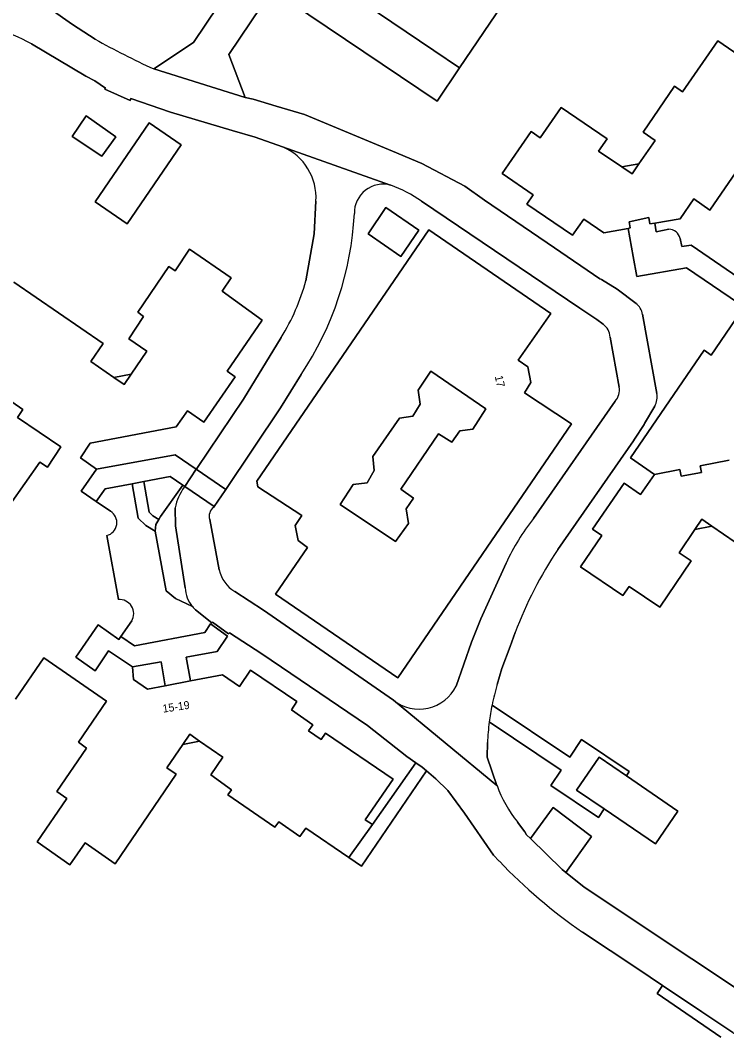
# Model space of a CAD drawing. Extents: x 158132 to 159664, y 385256 to 387218.
# Drawn here: x 159268.1 to 159356.5, y 385997.5 to 386123.9 of the extents above; entities that cross this region are included whole.
import ezdxf

# ---------------------------------------------------------------- set-up
doc = ezdxf.new("R2010")
doc.units = 0
for name, color, linetype in [('IMGEO_Erf', 7, 'Continuous'), ('IMGEO_Groenvoorziening', 7, 'Continuous'), ('IMGEO_Pand', 7, 'Continuous'), ('IMGEO_Pand_nummerreeks', 7, 'Continuous'), ('IMGEO_Pand_overbouw', 7, 'Continuous'), ('IMGEO_Parkeervlak_open', 7, 'Continuous'), ('IMGEO_Rijbaan_lokaal_gesloten', 7, 'Continuous'), ('IMGEO_Rijbaan_lokaal_open', 7, 'Continuous'), ('IMGEO_Voetpad_open', 7, 'Continuous')]:
    doc.layers.add(name, color=color, linetype=linetype)

msp = doc.modelspace()

# ---------------------------------------------------------------- linework, layer by layer
at = {"layer": 'IMGEO_Erf'}
for points in [[(159343.38, 386105.59), (159344.67, 386104.72), (159345.53, 386105.96)], [(159311.64, 386097.21), (159313.88, 386100.48), (159317.99, 386097.66), (159315.76, 386094.39)], [(159304.07, 386058.01), (159302.92, 386058.89), (159302.53, 386060.76), (159303.35, 386062.02), (159297.85, 386065.6), (159297.72, 386066.29), (159319.25, 386097.72), (159334.52, 386087.24), (159330.43, 386081.4), (159331.64, 386080.57), (159332.01, 386078.61), (159331.22, 386077.34), (159337.1, 386073.46), (159315.37, 386041.72), (159300.08, 386052.17)], [(159282.02, 386079.67), (159279.83, 386079.26), (159281.13, 386078.37)], [(159319.51, 386080.03), (159317.92, 386077.68), (159318.15, 386075.9), (159317.24, 386074.44), (159315.56, 386074.17), (159312.23, 386069.39), (159312.42, 386067.65), (159311.55, 386066.1), (159309.77, 386065.9), (159308.16, 386063.39), (159315.06, 386058.75), (159316.71, 386061.02), (159316.42, 386062.85), (159317.32, 386064.16), (159315.75, 386065.3), (159320.46, 386072.2), (159322.13, 386071.19), (159323.13, 386072.6), (159324.73, 386072.79), (159326.38, 386075.35)], [(159288.48, 386065.79), (159286.91, 386066.86), (159283.6, 386066.24), (159284.26, 386062.42), (159284.74, 386061.95), (159285.47, 386061.5), (159285.7, 386061.87)], [(159354.64, 386060.67), (159353.37, 386061.54), (159352.51, 386060.27)], [(159286.27, 386040.73), (159285.77, 386043.7), (159282.16, 386043.08), (159282.32, 386041.52), (159284.07, 386040.32)], [(159288.48, 386033.4), (159290.58, 386033.81), (159289.35, 386034.67)]]:
    msp.add_lwpolyline(points, close=True, dxfattribs=at)
for points in [[(159341.04, 386085.92), (159340.24, 386086.49), (159338.14, 386087.92), (159318.33, 386101.28)], [(159349.25, 386097.78), (159347.68, 386097.45), (159347.5, 386098.55), (159346.9, 386098.45), (159346.76, 386099.24), (159344.29, 386098.71), (159344.42, 386097.94), (159344.16, 386097.89), (159344.79, 386094.36), (159345.24, 386091.86), (159351.47, 386092.96), (159357.99, 386088.53), (159358.22, 386087.41), (159360.15, 386090.24), (159352.04, 386095.79), (159350.88, 386095.61), (159350.69, 386096.64)], [(159343.05, 386078.05), (159341.93, 386084.31)], [(159303.27, 386079.64), (159300.68, 386075.48), (159293.87, 386065.25), (159293.79, 386065.14), (159292.4, 386063.12), (159292.32, 386063.02)], [(159332.33, 386061.62), (159342.55, 386076.3)], [(159289.67, 386050.63), (159287.54, 386051.65), (159286.41, 386052.6), (159285.01, 386060.05), (159283.83, 386060.77), (159282.88, 386061.69), (159282.14, 386065.97), (159278.77, 386065.34), (159277.63, 386063.76), (159279.42, 386062.54)], [(159291.84, 386061.5), (159293.03, 386055.21)], [(159278.96, 386059.5), (159280.41, 386051.49)], [(159322.67, 386040.68), (159324.6, 386046.17), (159325.76, 386049.08), (159327.4, 386052.75), (159328.9, 386056.06)], [(159294.99, 386052.52), (159298.58, 386050.18), (159314.83, 386038.94)], [(159298.36, 386044.7), (159294.33, 386047.36), (159294.19, 386047.22), (159292.17, 386048.69), (159292.11, 386048.58), (159290.06, 386050.21)], [(159282.08, 386048.83), (159280.74, 386046.88), (159282.42, 386045.71), (159291.21, 386047.37), (159291.95, 386048.45), (159294.08, 386046.91), (159292.76, 386044.99), (159288.89, 386044.29), (159289.43, 386041.33), (159293.44, 386042.08), (159295.55, 386040.63), (159296.96, 386042.66), (159302.74, 386038.75), (159302.05, 386037.7), (159304.73, 386035.83), (159304.21, 386035.09), (159305.76, 386034.03), (159306.3, 386034.79), (159314.77, 386029.04), (159311.3, 386023.98), (159312.18, 386023.39), (159317.63, 386031.1), (159316.51, 386031.9), (159311.58, 386035.75), (159298.36, 386044.7)]]:
    msp.add_lwpolyline(points, dxfattribs=at)
for centre, radius, start, end in [((159313.52, 386099.82), 3.59, 74.6472, 181.3944), ((159308.31, 386086.58), 17.8, 55.6991, 69.7327), ((159270.35, 386101.72), 39.63, 326.1427, 357.1243), ((159349.27, 386096.33), 1.44, 12.0964, 91.081), ((159339.73, 386084.14), 2.21, 4.4468, 53.6926), ((159340.96, 386077.7), 2.12, 318.7172, 9.5991), ((159293.12, 386061.93), 1.35, 126.2293, 198.6545), ((159278.55, 386061.12), 1.67, 284.0563, 58.6242), ((159353.6, 386044.66), 27.2, 141.4288, 155.2241), ((159297.1, 386056.12), 4.18, 192.6758, 239.5387), ((159280.56, 386049.73), 1.77, 329.3209, 95.1105), ((159292.73, 386053.09), 3.93, 218.819, 227.2504), ((159318.04, 386042.98), 5.17, 231.5281, 333.5898)]:
    msp.add_arc(centre, radius, start, end, dxfattribs=at)
at = {"layer": 'IMGEO_Groenvoorziening'}
for points in [[(159335.95, 386136.95), (159323.1, 386117.95), (159320.28, 386113.77), (159299.63, 386127.71), (159294.22, 386119.61), (159296.27, 386114.24), (159297.27, 386114.02), (159300.16, 386113.16), (159303.71, 386112.11), (159314.7, 386107.55), (159318.37, 386106), (159323.74, 386103.16), (159326.21, 386101.41), (159334.98, 386095.47), (159340.64, 386091.6), (159340.83, 386091.48), (159342.82, 386090.3), (159345.16, 386088.49)], [(159284.83, 386117.81), (159289.8, 386121.12), (159295.91, 386130.21)], [(159269.49, 386127.04), (159274.68, 386123.36), (159277.5, 386121.54)], [(159300.96, 386108.09), (159297.51, 386109.27), (159294.64, 386110.12), (159286.92, 386112.41), (159281.99, 386114.1), (159281.87, 386113.87), (159278.73, 386115.28), (159278.8, 386115.43), (159277.49, 386116.31), (159276.36, 386116.9), (159269.53, 386120.94)], [(159347.56, 386108.88), (159346.06, 386109.9), (159349.99, 386115.64), (159350.99, 386114.96), (159355.38, 386121.31), (159358.06, 386119.48), (159358.15, 386119.59), (159359.43, 386118.64), (159359.56, 386118.8), (159362.52, 386116.78), (159359.88, 386112.88), (159361, 386112.06), (159359.19, 386109.35), (159360.84, 386108.18), (159358.78, 386105.2), (159358.15, 386105.62), (159354.39, 386100.18), (159352.38, 386101.59), (159350.66, 386099.08), (159347.5, 386098.55), (159347.68, 386097.45), (159349.25, 386097.78)], [(159357.99, 386088.53), (159351.47, 386092.96), (159345.24, 386091.86), (159344.79, 386094.36), (159344.16, 386097.89), (159341.12, 386097.34), (159338.63, 386099.05), (159337.2, 386097.02), (159331.52, 386100.9), (159332.29, 386102.07), (159328.43, 386104.75), (159332.03, 386109.98), (159333.19, 386109.21), (159335.8, 386113.01), (159341.54, 386109.07), (159340.47, 386107.55), (159343.38, 386105.59), (159345.53, 386105.96), (159347.56, 386108.88)], [(159303.85, 386091.34), (159304.92, 386097.21), (159305.13, 386101.28)], [(159350.69, 386096.64), (159350.88, 386095.61), (159352.04, 386095.79), (159360.15, 386090.24)], [(159267.32, 386091.16), (159278.51, 386083.48), (159276.96, 386081.24), (159279.83, 386079.26), (159282.02, 386079.67), (159283.99, 386082.54), (159281.73, 386084.09), (159283.56, 386086.86), (159282.83, 386087.4), (159286.72, 386093.11), (159287.51, 386092.58), (159289.32, 386095.28), (159294.51, 386091.71), (159293.41, 386090.03), (159298.38, 386086.42), (159294.02, 386080.05), (159295.04, 386079.34), (159291.09, 386073.68), (159289.05, 386075.07), (159287.64, 386073.08), (159276.87, 386071.04), (159275.67, 386069.23), (159277.67, 386067.81), (159287.5, 386069.59), (159290.15, 386067.78), (159290.22, 386067.89), (159296.05, 386076.54), (159300.78, 386084.27)], [(159357.54, 386058.69), (159354.64, 386060.67), (159352.51, 386060.27), (159350.55, 386057.34), (159352.05, 386056.33), (159348.13, 386050.57), (159344.31, 386053.12), (159343.5, 386052), (159338.23, 386055.58), (159340.9, 386059.52), (159339.73, 386060.28), (159343.67, 386066.03), (159345.73, 386064.62), (159347.45, 386067.15), (159344.46, 386069.2), (159353.67, 386082.67), (159354.56, 386082.06), (159358.22, 386087.41)], [(159345.97, 386087.15), (159347.76, 386077.26)], [(159266.82, 386063.33), (159270.59, 386068.68), (159271.54, 386068.04), (159273.23, 386070.6), (159267.78, 386074.27), (159268.46, 386075.27), (159262.08, 386079.66)], [(159347.5, 386075.67), (159346.23, 386073.49), (159346.18, 386073.39), (159344.97, 386071.54), (159344.83, 386071.35), (159335.38, 386057.77)], [(159330.04, 386047.37), (159329.4, 386045.64), (159328.38, 386042.89), (159327.79, 386040.9)], [(159328.06, 386018.79), (159327.35, 386019.57), (159323.69, 386024.8), (159321.62, 386027.66), (159320.14, 386029.09), (159318.95, 386030.1), (159310.82, 386018.18), (159309.25, 386019.25), (159303.84, 386022.94), (159303.11, 386021.91), (159300.48, 386023.72), (159299.98, 386023.05), (159294.11, 386027.11), (159294.56, 386027.73), (159291.98, 386029.58), (159293.49, 386031.79), (159290.58, 386033.81), (159288.48, 386033.4), (159286.49, 386030.49), (159287.63, 386029.66), (159280.03, 386018.47), (159276.27, 386021.08), (159274.35, 386018.34), (159270.24, 386021.21), (159273.95, 386026.65), (159272.7, 386027.51), (159276.43, 386032.95), (159275.41, 386033.66), (159278.92, 386038.79), (159271.08, 386044.23), (159267.53, 386039.05)], [(159327.15, 386038.3), (159336.86, 386031.79), (159338.35, 386034.02), (159344.32, 386030.02), (159343.95, 386029.47), (159350.4, 386025.07), (159347.58, 386020.96), (159341.17, 386025.33), (159340.46, 386024.26), (159334.49, 386028.26), (159335.78, 386030.19), (159326.8, 386036.2)], [(159326.57, 386033.62), (159326.52, 386031.8), (159327.77, 386028.26)], [(159330.33, 386023.7), (159331.27, 386022.46), (159331.46, 386022.11), (159331.94, 386021.63), (159334.78, 386025.51), (159339.6, 386021.9), (159336.36, 386017.41), (159338.61, 386015.61), (159349.29, 386008.47), (159354.98, 386004.72), (159362.07, 386000), (159362.67, 385999.6), (159365, 385998.05), (159365.02, 385998.03), (159366.81, 385996.83), (159367.48, 385996.37)], [(159355.76, 385996.83), (159347.79, 386002.25), (159348.48, 386003.28), (159345.38, 386005.36), (159338.45, 386009.93)]]:
    msp.add_lwpolyline(points, dxfattribs=at)
for points in [[(159278.36, 386106.9), (159274.62, 386109.39), (159276.38, 386111.95), (159280.1, 386109.33)], [(159277.51, 386101.19), (159284.25, 386111.07), (159288.26, 386108.34), (159281.52, 386098.46)]]:
    msp.add_lwpolyline(points, close=True, dxfattribs=at)
for centre, radius, start, end in [((159260.07, 386104.26), 19.18, 60.4425, 75.3025), ((159329.26, 386214.28), 106.21, 240.8363, 245.2733), ((159298.22, 386101.73), 6.92, 356.2434, 66.664), ((159349.27, 386096.33), 1.44, 12.0964, 91.081), ((159279.05, 386097.91), 25.66, 327.8886, 345.1676), ((159343.93, 386086.83), 2.06, 8.7647, 53.5626), ((159345.52, 386076.81), 2.28, 330.159, 11.5367), ((159378.27, 386029.15), 51.56, 146.2907, 159.3077), ((159358.35, 386032.1), 31.81, 163.9268, 168.7575), ((159359.21, 386031.92), 32.69, 172.4767, 177.0142), ((159342.69, 386033.65), 15.86, 199.8565, 218.834), ((159378.7, 386067.59), 70.32, 223.9382, 235.0831)]:
    msp.add_arc(centre, radius, start, end, dxfattribs=at)
at = {"layer": 'IMGEO_Pand'}
for points in [[(159358.06, 386119.48), (159355.38, 386121.31), (159350.99, 386114.96), (159349.99, 386115.64), (159346.06, 386109.9), (159347.56, 386108.88), (159345.53, 386105.96), (159344.67, 386104.72), (159343.38, 386105.59), (159340.47, 386107.55), (159341.54, 386109.07), (159335.8, 386113.01), (159333.19, 386109.21), (159332.03, 386109.98), (159328.43, 386104.75), (159332.29, 386102.07), (159331.52, 386100.9), (159337.2, 386097.02), (159338.63, 386099.05), (159341.12, 386097.34), (159344.16, 386097.89), (159344.42, 386097.94), (159344.29, 386098.71), (159346.76, 386099.24), (159346.9, 386098.45), (159347.5, 386098.55), (159350.66, 386099.08), (159352.38, 386101.59), (159354.39, 386100.18), (159358.15, 386105.62)], [(159279.42, 386062.54), (159277.63, 386063.76), (159275.78, 386065.03), (159277.67, 386067.81), (159275.67, 386069.23), (159276.87, 386071.04), (159287.64, 386073.08), (159289.05, 386075.07), (159291.09, 386073.68), (159295.04, 386079.34), (159294.02, 386080.05), (159298.38, 386086.42), (159293.41, 386090.03), (159294.51, 386091.71), (159289.32, 386095.28), (159287.51, 386092.58), (159286.72, 386093.11), (159282.83, 386087.4), (159283.56, 386086.86), (159281.73, 386084.09), (159283.99, 386082.54), (159282.02, 386079.67), (159281.13, 386078.37), (159279.83, 386079.26), (159276.96, 386081.24), (159278.51, 386083.48), (159267.32, 386091.16)], [(159358.22, 386087.41), (159354.56, 386082.06), (159353.67, 386082.67), (159344.46, 386069.2), (159347.45, 386067.15), (159350.65, 386067.76), (159350.82, 386066.93), (159353.33, 386067.39), (159353.17, 386068.21), (159356.81, 386068.93)], [(159262.08, 386079.66), (159268.46, 386075.27), (159267.78, 386074.27), (159273.23, 386070.6), (159271.54, 386068.04), (159270.59, 386068.68), (159266.82, 386063.33)], [(159356.81, 386068.93), (159353.17, 386068.21), (159353.33, 386067.39), (159350.82, 386066.93), (159350.65, 386067.76), (159347.45, 386067.15), (159345.73, 386064.62), (159343.67, 386066.03), (159339.73, 386060.28), (159340.9, 386059.52), (159338.23, 386055.58), (159343.5, 386052), (159344.31, 386053.12), (159348.13, 386050.57), (159352.05, 386056.33), (159350.55, 386057.34), (159352.51, 386060.27), (159353.37, 386061.54), (159354.64, 386060.67), (159357.54, 386058.69)], [(159280.41, 386051.49), (159278.96, 386059.5)], [(159267.53, 386039.05), (159271.08, 386044.23), (159278.92, 386038.79), (159275.41, 386033.66), (159276.43, 386032.95), (159272.7, 386027.51), (159273.95, 386026.65), (159270.24, 386021.21), (159274.35, 386018.34), (159276.27, 386021.08), (159280.03, 386018.47), (159287.63, 386029.66), (159286.49, 386030.49), (159288.48, 386033.4), (159289.35, 386034.67), (159290.58, 386033.81), (159293.49, 386031.79), (159291.98, 386029.58), (159294.56, 386027.73), (159294.11, 386027.11), (159299.98, 386023.05), (159300.48, 386023.72), (159303.11, 386021.91), (159303.84, 386022.94), (159309.25, 386019.25), (159312.18, 386023.39), (159311.3, 386023.98), (159314.77, 386029.04), (159306.3, 386034.79), (159305.76, 386034.03), (159304.21, 386035.09), (159304.73, 386035.83), (159302.05, 386037.7), (159302.74, 386038.75), (159296.96, 386042.66), (159295.55, 386040.63), (159293.44, 386042.08), (159289.43, 386041.33), (159286.27, 386040.73), (159284.07, 386040.32), (159282.32, 386041.52), (159282.16, 386043.08), (159279.19, 386045.1), (159277.51, 386042.61), (159275.11, 386044.3), (159277.89, 386048.33), (159280.47, 386046.49), (159280.74, 386046.88), (159282.08, 386048.83)]]:
    msp.add_lwpolyline(points, dxfattribs=at)
for points in [[(159278.36, 386106.9), (159280.1, 386109.33), (159276.38, 386111.95), (159274.62, 386109.39)], [(159277.51, 386101.19), (159281.52, 386098.46), (159288.26, 386108.34), (159284.25, 386111.07)], [(159315.76, 386094.39), (159317.99, 386097.66), (159313.88, 386100.48), (159311.64, 386097.21)], [(159337.1, 386073.46), (159331.22, 386077.34), (159332.01, 386078.61), (159331.64, 386080.57), (159330.43, 386081.4), (159334.52, 386087.24), (159319.25, 386097.72), (159297.72, 386066.29), (159297.85, 386065.6), (159303.35, 386062.02), (159302.53, 386060.76), (159302.92, 386058.89), (159304.07, 386058.01), (159300.08, 386052.17), (159315.37, 386041.72)], [(159319.51, 386080.03), (159326.38, 386075.35), (159324.73, 386072.79), (159323.13, 386072.6), (159322.13, 386071.19), (159320.46, 386072.2), (159315.75, 386065.3), (159317.32, 386064.16), (159316.42, 386062.85), (159316.71, 386061.02), (159315.06, 386058.75), (159308.16, 386063.39), (159309.77, 386065.9), (159311.55, 386066.1), (159312.42, 386067.65), (159312.23, 386069.39), (159315.56, 386074.17), (159317.24, 386074.44), (159318.15, 386075.9), (159317.92, 386077.68)], [(159343.95, 386029.47), (159340.54, 386031.8), (159337.72, 386027.68), (159341.17, 386025.33), (159347.58, 386020.96), (159350.4, 386025.07)]]:
    msp.add_lwpolyline(points, close=True, dxfattribs=at)
for centre, radius, start, end in [((159278.55, 386061.12), 1.67, 284.0563, 58.6242), ((159280.56, 386049.73), 1.77, 329.3209, 95.1105)]:
    msp.add_arc(centre, radius, start, end, dxfattribs=at)
at = {"layer": 'IMGEO_Pand_overbouw'}
for points in [[(159345.53, 386105.96), (159343.38, 386105.59), (159344.67, 386104.72)], [(159279.83, 386079.26), (159281.13, 386078.37), (159282.02, 386079.67)], [(159352.51, 386060.27), (159354.64, 386060.67), (159353.37, 386061.54)], [(159288.48, 386033.4), (159290.58, 386033.81), (159289.35, 386034.67), (159288.48, 386033.4)]]:
    msp.add_lwpolyline(points, close=True, dxfattribs=at)
for points in [[(159349.25, 386097.78), (159347.68, 386097.45), (159347.5, 386098.55), (159346.9, 386098.45), (159346.76, 386099.24), (159344.29, 386098.71), (159344.42, 386097.94), (159344.16, 386097.89), (159344.79, 386094.36), (159345.24, 386091.86), (159351.47, 386092.96), (159357.99, 386088.53), (159358.22, 386087.41), (159360.15, 386090.24), (159352.04, 386095.79)], [(159352.04, 386095.79), (159350.88, 386095.61), (159350.69, 386096.64)]]:
    msp.add_lwpolyline(points, dxfattribs=at)
msp.add_arc((159349.27, 386096.33), 1.44, 12.0964, 91.081, dxfattribs=at)
at = {"layer": 'IMGEO_Parkeervlak_open'}
for points in [[(159299.63, 386127.71), (159320.28, 386113.77), (159323.1, 386117.95), (159319.88, 386120.12), (159302.45, 386131.89)], [(159331.94, 386021.63), (159335.91, 386017.76), (159336.36, 386017.41), (159339.6, 386021.9), (159334.78, 386025.51)]]:
    msp.add_lwpolyline(points, close=True, dxfattribs=at)
for points in [[(159288.64, 386065.53), (159288.71, 386065.63), (159288.48, 386065.79), (159285.7, 386061.87), (159285.47, 386061.5), (159285.09, 386060.88), (159285.01, 386060.05), (159286.41, 386052.6), (159287.54, 386051.65), (159289.67, 386050.63)], [(159287.56, 386060.73), (159287.53, 386062.97)], [(159288.78, 386052.98), (159287.56, 386060.73)]]:
    msp.add_lwpolyline(points, dxfattribs=at)
for centre, radius, start, end in [((159293.6, 386061.86), 6.17, 143.5055, 169.6334), ((159292.79, 386053.15), 4.02, 182.547, 218.918)]:
    msp.add_arc(centre, radius, start, end, dxfattribs=at)
at = {"layer": 'IMGEO_Rijbaan_lokaal_gesloten'}
for points in [[(159277.5, 386121.54), (159274.68, 386123.36), (159269.49, 386127.04)], [(159269.53, 386120.94), (159276.36, 386116.9), (159277.49, 386116.31), (159278.8, 386115.43), (159278.73, 386115.28), (159281.87, 386113.87), (159281.99, 386114.1), (159286.92, 386112.41), (159294.64, 386110.12), (159297.51, 386109.27), (159300.96, 386108.09), (159314.47, 386103.28)], [(159345.16, 386088.49), (159342.82, 386090.3), (159340.83, 386091.48), (159340.64, 386091.6), (159334.98, 386095.47), (159326.21, 386101.41), (159323.74, 386103.16), (159318.37, 386106), (159314.7, 386107.55), (159303.71, 386112.11), (159300.16, 386113.16), (159297.27, 386114.02), (159296.27, 386114.24), (159284.83, 386117.81)], [(159314.47, 386103.28), (159300.96, 386108.09)], [(159305.13, 386101.28), (159304.92, 386097.21), (159303.85, 386091.34)], [(159318.33, 386101.28), (159338.14, 386087.92), (159340.24, 386086.49), (159341.04, 386085.92)], [(159347.76, 386077.26), (159345.97, 386087.15)], [(159341.93, 386084.31), (159343.05, 386078.05)], [(159300.78, 386084.27), (159296.05, 386076.54), (159290.22, 386067.89), (159290.15, 386067.78), (159293.87, 386065.25), (159300.68, 386075.48), (159303.27, 386079.64)], [(159342.55, 386076.3), (159332.33, 386061.62)], [(159335.38, 386057.77), (159344.83, 386071.35), (159344.97, 386071.54), (159346.18, 386073.39), (159346.23, 386073.49), (159347.5, 386075.67)], [(159292.32, 386063.02), (159292.4, 386063.12), (159288.71, 386065.63), (159288.64, 386065.53)], [(159287.53, 386062.97), (159287.56, 386060.73), (159288.78, 386052.98)], [(159293.03, 386055.21), (159291.84, 386061.5)], [(159328.9, 386056.06), (159327.4, 386052.75), (159325.76, 386049.08), (159324.6, 386046.17), (159322.67, 386040.68)], [(159298.58, 386050.18), (159294.99, 386052.52)], [(159290.06, 386050.21), (159292.11, 386048.58), (159292.17, 386048.69), (159294.19, 386047.22), (159294.33, 386047.36), (159298.36, 386044.7), (159311.58, 386035.75), (159316.51, 386031.9), (159317.63, 386031.1), (159318.43, 386030.54), (159318.95, 386030.1), (159320.14, 386029.09), (159321.62, 386027.66), (159323.69, 386024.8), (159327.35, 386019.57), (159328.06, 386018.79)], [(159327.77, 386028.26), (159314.83, 386038.94), (159298.58, 386050.18)], [(159327.79, 386040.9), (159328.38, 386042.89), (159329.4, 386045.64), (159330.04, 386047.37)], [(159314.83, 386038.94), (159327.77, 386028.26), (159326.52, 386031.8), (159326.57, 386033.62)], [(159338.45, 386009.93), (159345.38, 386005.36), (159348.48, 386003.28), (159353.37, 386000), (159357.27, 385997.38), (159359.91, 385995.65), (159362.06, 385994.25), (159362.35, 385994.06), (159363.93, 385993.02), (159366.81, 385996.83), (159365.02, 385998.03), (159365, 385998.05), (159362.67, 385999.6), (159362.07, 386000), (159354.98, 386004.72), (159349.29, 386008.47), (159338.61, 386015.61), (159336.36, 386017.41), (159335.91, 386017.76), (159331.94, 386021.63), (159331.46, 386022.11), (159331.27, 386022.46), (159330.33, 386023.7)]]:
    msp.add_lwpolyline(points, dxfattribs=at)
msp.add_lwpolyline([(159290.15, 386067.78), (159288.71, 386065.63), (159292.4, 386063.12), (159293.79, 386065.14), (159293.87, 386065.25)], close=True, dxfattribs=at)
for centre, radius, start, end in [((159260.07, 386104.26), 19.18, 60.4425, 75.3025), ((159329.26, 386214.28), 106.21, 240.8363, 245.2733), ((159298.22, 386101.73), 6.92, 356.2434, 66.664), ((159313.52, 386099.82), 3.59, 74.6472, 181.3944), ((159308.31, 386086.58), 17.8, 55.6991, 69.7327), ((159270.35, 386101.72), 39.63, 326.1427, 357.1243), ((159279.05, 386097.91), 25.66, 327.8886, 345.1676), ((159343.93, 386086.83), 2.06, 8.7647, 53.5626), ((159339.73, 386084.14), 2.21, 4.4468, 53.6926), ((159340.96, 386077.7), 2.12, 318.7172, 9.5991), ((159345.52, 386076.81), 2.28, 330.159, 11.5367), ((159293.6, 386061.86), 6.17, 143.5055, 169.6334), ((159293.12, 386061.93), 1.35, 126.2293, 198.6545), ((159353.6, 386044.66), 27.2, 141.4288, 155.2241), ((159378.27, 386029.15), 51.56, 146.2907, 159.3077), ((159297.1, 386056.12), 4.18, 192.6758, 239.5387), ((159292.79, 386053.15), 4.02, 182.547, 218.918), ((159292.73, 386053.09), 3.93, 218.819, 227.2504), ((159318.04, 386042.98), 5.17, 231.5281, 333.5898), ((159358.35, 386032.1), 31.81, 163.9268, 168.7575), ((159358.94, 386031.93), 32.42, 168.6757, 172.4351), ((159359.21, 386031.92), 32.69, 172.4767, 177.0142), ((159342.69, 386033.65), 15.86, 199.8565, 218.834), ((159378.7, 386067.59), 70.32, 223.9382, 235.0831)]:
    msp.add_arc(centre, radius, start, end, dxfattribs=at)
at = {"layer": 'IMGEO_Rijbaan_lokaal_open'}
msp.add_lwpolyline([(159335.95, 386136.95), (159302.5, 386159.58), (159298.98, 386161.95), (159286.13, 386142.91), (159298.74, 386134.39), (159295.91, 386130.21), (159289.8, 386121.12), (159284.83, 386117.81), (159296.27, 386114.24), (159294.22, 386119.61), (159299.63, 386127.71), (159302.45, 386131.89), (159319.88, 386120.12), (159323.1, 386117.95)], close=True, dxfattribs=at)
at = {"layer": 'IMGEO_Voetpad_open'}
for points in [[(159286.91, 386066.86), (159288.48, 386065.79), (159288.71, 386065.63), (159290.15, 386067.78), (159287.5, 386069.59), (159277.67, 386067.81), (159275.78, 386065.03), (159277.63, 386063.76), (159278.77, 386065.34), (159282.14, 386065.97), (159283.6, 386066.24)], [(159283.6, 386066.24), (159282.14, 386065.97), (159282.88, 386061.69), (159283.83, 386060.77), (159285.01, 386060.05), (159285.09, 386060.88), (159285.47, 386061.5), (159284.74, 386061.95), (159284.26, 386062.42)], [(159282.16, 386043.08), (159285.77, 386043.7), (159286.27, 386040.73), (159289.43, 386041.33), (159288.89, 386044.29), (159292.76, 386044.99), (159294.08, 386046.91), (159291.95, 386048.45), (159291.21, 386047.37), (159282.42, 386045.71), (159280.74, 386046.88), (159280.47, 386046.49), (159277.89, 386048.33), (159275.11, 386044.3), (159277.51, 386042.61), (159279.19, 386045.1)], [(159318.95, 386030.1), (159318.43, 386030.54), (159317.63, 386031.1), (159312.18, 386023.39), (159309.25, 386019.25), (159310.82, 386018.18)]]:
    msp.add_lwpolyline(points, close=True, dxfattribs=at)
for points in [[(159340.54, 386031.8), (159343.95, 386029.47), (159344.32, 386030.02), (159338.35, 386034.02), (159336.86, 386031.79), (159327.15, 386038.3)], [(159326.8, 386036.2), (159335.78, 386030.19), (159334.49, 386028.26), (159340.46, 386024.26), (159341.17, 386025.33), (159337.72, 386027.68), (159340.54, 386031.8)], [(159357.27, 385997.38), (159353.37, 386000), (159348.48, 386003.28), (159347.79, 386002.25), (159355.76, 385996.83)]]:
    msp.add_lwpolyline(points, dxfattribs=at)
msp.add_arc((159358.94, 386031.93), 32.42, 168.6757, 172.4351, dxfattribs=at)

# ---------------------------------------------------------------- texts
at = {"layer": 'IMGEO_Pand_nummerreeks'}
for s, rotation, p in [('17', 282.7008, (159327.48, 386079.4)), ('15-19', 8.5351, (159286.01, 386037.36))]:
    msp.add_text(s, height=1, rotation=rotation, dxfattribs=at).set_placement(p)

doc.saveas('drawing.dxf')
